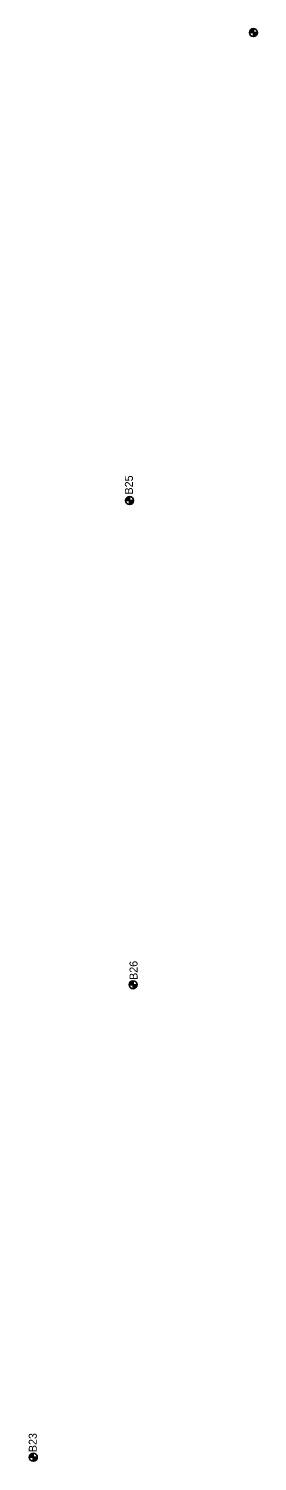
# Model space of a CAD drawing. Extents: x 331323 to 388339, y 121519 to 205315.
# Drawn here: x 361587 to 361873, y 141536 to 143326 of the extents above; entities that cross this region are included whole.
import ezdxf

# ---------------------------------------------------------------- set-up
doc = ezdxf.new("R2010")
doc.units = 0
for name, color, linetype in [('E_SOIL_BORE1 [KAPUR_CADDS_LEVELS]', 7, 'Continuous'), ('E_SOIL_BORE2 [KAPUR_CADDS_LEVELS]', 7, 'Continuous'), ('P_MARK', 7, 'Continuous')]:
    doc.layers.add(name, color=color, linetype=linetype)

msp = doc.modelspace()

# ---------------------------------------------------------------- linework, layer by layer
at = {"layer": 'P_MARK'}
for p, q in [((361863, 143321.3), (361873, 143321.3)), ((361868, 143326.3), (361868, 143316.3)), ((361708.4, 142736.6), (361718.4, 142736.6)), ((361713.4, 142741.6), (361713.4, 142731.6)), ((361717.8, 142136.6), (361717.8, 142126.6)), ((361712.8, 142131.6), (361722.8, 142131.6)), ((361593.1, 141546), (361593.1, 141536)), ((361588.1, 141541), (361598.1, 141541))]:
    msp.add_line(p, q, dxfattribs=at)
for centre in [(361868, 143321.3), (361713.4, 142736.6), (361717.8, 142131.6), (361593.1, 141541)]:
    msp.add_circle(centre, 5, dxfattribs=at)
for centre, radius, start, end in [((361868, 143321.3), 4.5, 89.9869, 179.9869), ((361868, 143321.3), 4, 89.9869, 179.9869), ((361868, 143321.3), 3.5, 89.9869, 179.9869), ((361868, 143321.3), 3, 89.9869, 179.9869), ((361868, 143321.3), 2.5, 89.9869, 179.9869), ((361868, 143321.3), 2, 89.9869, 179.9869), ((361868, 143321.3), 1.5, 89.9869, 179.9869), ((361868, 143321.3), 1, 89.9869, 179.9869), ((361868, 143321.3), 0.5, 89.9869, 179.9869), ((361868, 143321.3), 4.5, 269.9869, 359.9869), ((361868, 143321.3), 4, 269.9869, 359.9869), ((361868, 143321.3), 3.5, 269.9869, 359.9869), ((361868, 143321.3), 3, 269.9869, 359.9869), ((361868, 143321.3), 2.5, 269.9869, 359.9869), ((361868, 143321.3), 2, 269.9869, 359.9869), ((361868, 143321.3), 1.5, 269.9869, 359.9869), ((361868, 143321.3), 1, 269.9869, 359.9869), ((361868, 143321.3), 0.5, 269.9869, 359.9869), ((361713.4, 142736.6), 4.5, 89.9869, 179.9869), ((361713.4, 142736.6), 4, 89.9869, 179.9869), ((361713.4, 142736.6), 3.5, 89.9869, 179.9869), ((361713.4, 142736.6), 3, 89.9869, 179.9869), ((361713.4, 142736.6), 2.5, 89.9869, 179.9869), ((361713.4, 142736.6), 2, 89.9869, 179.9869), ((361713.4, 142736.6), 1.5, 89.9869, 179.9869), ((361713.4, 142736.6), 1, 89.9869, 179.9869), ((361713.4, 142736.6), 0.5, 89.9869, 179.9869), ((361713.4, 142736.6), 4.5, 269.9869, 359.9869), ((361713.4, 142736.6), 4, 269.9869, 359.9869), ((361713.4, 142736.6), 3.5, 269.9869, 359.9869), ((361713.4, 142736.6), 3, 269.9869, 359.9869), ((361713.4, 142736.6), 2.5, 269.9869, 359.9869), ((361713.4, 142736.6), 2, 269.9869, 359.9869), ((361713.4, 142736.6), 1.5, 269.9869, 359.9869), ((361713.4, 142736.6), 1, 269.9869, 359.9869), ((361713.4, 142736.6), 0.5, 269.9869, 359.9869), ((361717.8, 142131.6), 4.5, 89.9869, 179.9869), ((361717.8, 142131.6), 4, 89.9869, 179.9869), ((361717.8, 142131.6), 3.5, 89.9869, 179.9869), ((361717.8, 142131.6), 3, 89.9869, 179.9869), ((361717.8, 142131.6), 2.5, 89.9869, 179.9869), ((361717.8, 142131.6), 2, 89.9869, 179.9869), ((361717.8, 142131.6), 1.5, 89.9869, 179.9869), ((361717.8, 142131.6), 1, 89.9869, 179.9869), ((361717.8, 142131.6), 0.5, 89.9869, 179.9869), ((361717.8, 142131.6), 4.5, 269.9869, 359.9869), ((361717.8, 142131.6), 4, 269.9869, 359.9869), ((361717.8, 142131.6), 3.5, 269.9869, 359.9869), ((361717.8, 142131.6), 3, 269.9869, 359.9869), ((361717.8, 142131.6), 2.5, 269.9869, 359.9869), ((361717.8, 142131.6), 2, 269.9869, 359.9869), ((361717.8, 142131.6), 1.5, 269.9869, 359.9869), ((361717.8, 142131.6), 1, 269.9869, 359.9869), ((361717.8, 142131.6), 0.5, 269.9869, 359.9869), ((361593.1, 141541), 4.5, 89.9869, 179.9869), ((361593.1, 141541), 4, 89.9869, 179.9869), ((361593.1, 141541), 3.5, 89.9869, 179.9869), ((361593.1, 141541), 3, 89.9869, 179.9869), ((361593.1, 141541), 2.5, 89.9869, 179.9869), ((361593.1, 141541), 2, 89.9869, 179.9869), ((361593.1, 141541), 1.5, 89.9869, 179.9869), ((361593.1, 141541), 1, 89.9869, 179.9869), ((361593.1, 141541), 0.5, 89.9869, 179.9869), ((361593.1, 141541), 4.5, 269.9869, 359.9869), ((361593.1, 141541), 4, 269.9869, 359.9869), ((361593.1, 141541), 3.5, 269.9869, 359.9869), ((361593.1, 141541), 3, 269.9869, 359.9869), ((361593.1, 141541), 2.5, 269.9869, 359.9869), ((361593.1, 141541), 2, 269.9869, 359.9869), ((361593.1, 141541), 1.5, 269.9869, 359.9869), ((361593.1, 141541), 1, 269.9869, 359.9869), ((361593.1, 141541), 0.5, 269.9869, 359.9869)]:
    msp.add_arc(centre, radius, start, end, dxfattribs=at)

# ---------------------------------------------------------------- texts
at = {"layer": 'E_SOIL_BORE1 [KAPUR_CADDS_LEVELS]'}
msp.add_text('B23', height=10, rotation=89.9869, dxfattribs=at).set_placement((361597.4, 141547.5))
at = {"layer": 'E_SOIL_BORE2 [KAPUR_CADDS_LEVELS]'}
for s, p in [('B25', (361717.5, 142744.2)), ('B26', (361723.3, 142137.6))]:
    msp.add_text(s, height=10, rotation=89.9869, dxfattribs=at).set_placement(p)

doc.saveas('drawing.dxf')
